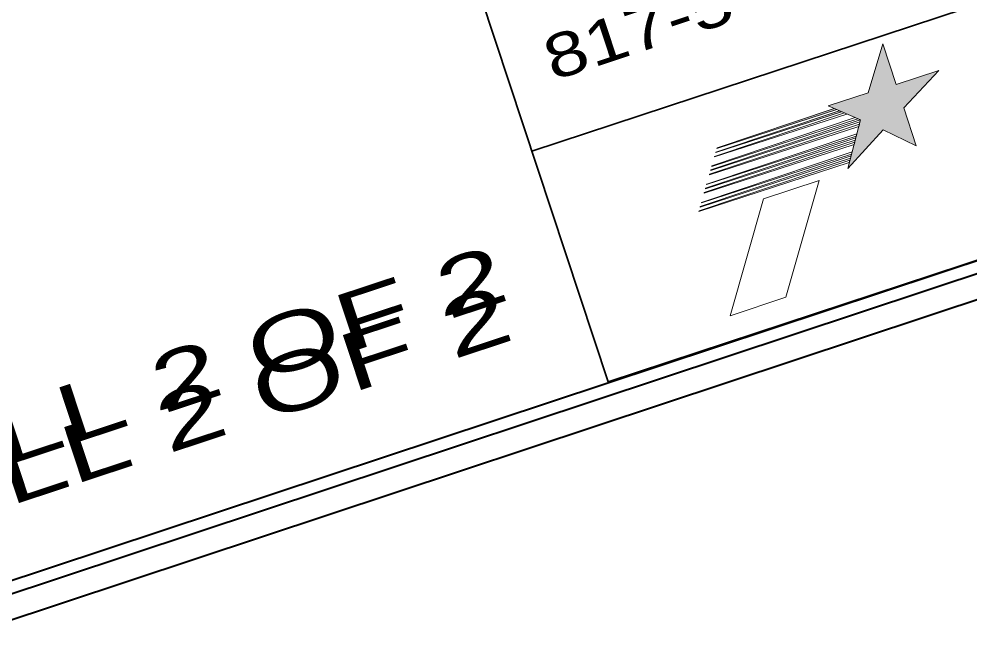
# Model space of a CAD drawing. Extents: x 2355803 to 2371254, y 6970215 to 6985302.
# Drawn here: x 2370231.3 to 2370614.5, y 6977989.2 to 6978236.6 of the extents above; entities that cross this region are included whole.
import ezdxf

# ---------------------------------------------------------------- set-up
doc = ezdxf.new("R2010")
doc.units = 0
doc.header["$LTSCALE"] = 7.1
doc.layers.add('19', color=7, linetype='Continuous', lineweight=13)
doc.layers.add('8', color=7, linetype='Continuous', lineweight=13)

msp = doc.modelspace()

# ---------------------------------------------------------------- hatches: boundary and pattern name
at = {"layer": '19'}
for points in [[(2370579.296, 6978226.596), (2370573.396, 6978206.854), (2370557.342, 6978201.552), (2370570.392, 6978195.93), (2370565.25, 6978176.42), (2370579.562, 6978191.926), (2370592.858, 6978185.542), (2370587.8, 6978200.856), (2370601.892, 6978215.84), (2370584.726, 6978210.162)], [(2370512.108, 6978182.992), (2370561.742, 6978199.652), (2370562.72, 6978199.22), (2370512.036, 6978182.78)], [(2370512.582, 6978184.658), (2370559.788, 6978200.482), (2370560.762, 6978200.09), (2370512.546, 6978184.424)]]:
    msp.add_hatch(color=256, dxfattribs=at).paths.add_polyline_path(points)
at = {"layer": '8'}
for points in [[(2370579.296, 6978226.596), (2370573.396, 6978206.854), (2370557.342, 6978201.552), (2370570.392, 6978195.93), (2370565.25, 6978176.42), (2370579.562, 6978191.926), (2370592.858, 6978185.542), (2370587.8, 6978200.856), (2370601.892, 6978215.84), (2370584.726, 6978210.162)], [(2370512.108, 6978182.992), (2370561.742, 6978199.652), (2370562.72, 6978199.22), (2370512.036, 6978182.78)], [(2370512.582, 6978184.658), (2370559.788, 6978200.482), (2370560.762, 6978200.09), (2370512.546, 6978184.424)]]:
    msp.add_hatch(color=256, dxfattribs=at).paths.add_polyline_path(points)

# ---------------------------------------------------------------- linework, layer by layer
at = {"layer": '19', "lineweight": 35}
for p, q in [((2370247.37, 6978760.29), (2370468.692, 6978090.342)), ((2371235.212, 6978343.566), (2370468.692, 6978090.342)), ((2370886.828, 6978331.606), (2370437.974, 6978183.324))]:
    msp.add_line(p, q, dxfattribs=at)
at = {"layer": '19', "lineweight": 40}
msp.add_lwpolyline([(2371235.04, 6978344.083), (2356889.216, 6973586.555), (2355819.061, 6976813.747)], dxfattribs=at)
at = {"layer": '19'}
for points in [[(2370579.296, 6978226.596), (2370573.396, 6978206.854), (2370557.342, 6978201.552), (2370570.392, 6978195.93), (2370565.25, 6978176.42), (2370579.562, 6978191.926), (2370592.858, 6978185.542), (2370587.8, 6978200.856), (2370601.892, 6978215.84), (2370584.726, 6978210.162)], [(2370511.594, 6978181.204), (2370563.88, 6978198.728), (2370564.84, 6978198.31), (2370511.57, 6978180.99)], [(2370512.108, 6978182.992), (2370561.742, 6978199.652), (2370562.72, 6978199.22), (2370512.036, 6978182.78)], [(2370512.582, 6978184.658), (2370559.788, 6978200.482), (2370560.762, 6978200.09), (2370512.546, 6978184.424)], [(2370509.55, 6978174.006), (2370569.96, 6978194.278), (2370569.704, 6978193.324), (2370509.528, 6978173.786)], [(2370510.038, 6978175.79), (2370570.166, 6978196), (2370570.38, 6978195.926), (2370570.158, 6978195.106), (2370510.002, 6978175.55)], [(2370510.528, 6978177.442), (2370568.26, 6978196.844), (2370569.354, 6978196.356), (2370510.48, 6978177.21)], [(2370508.414, 6978170.064), (2370568.926, 6978190.35), (2370568.682, 6978189.434), (2370508.36, 6978169.85)], [(2370507.43, 6978166.646), (2370568.014, 6978186.948), (2370567.77, 6978186.038), (2370507.39, 6978166.406)], [(2370507.918, 6978168.416), (2370568.48, 6978188.71), (2370568.248, 6978187.814), (2370507.894, 6978168.2)], [(2370506.298, 6978162.698), (2370566.99, 6978183.05), (2370566.756, 6978182.186), (2370506.248, 6978162.474)], [(2370505.322, 6978159.274), (2370566.09, 6978179.654), (2370565.846, 6978178.782), (2370505.258, 6978159.068)], [(2370505.802, 6978161.068), (2370566.566, 6978181.414), (2370566.33, 6978180.558), (2370505.766, 6978160.83)], [(2370531.304, 6978164.104), (2370517.858, 6978117.048), (2370540.252, 6978124.448), (2370553.682, 6978171.504)]]:
    msp.add_lwpolyline(points, close=True, dxfattribs=at)
at = {"layer": '8', "lineweight": 35}
for p, q in [((2370247.37, 6978760.29), (2370468.692, 6978090.342)), ((2371235.212, 6978343.566), (2370468.692, 6978090.342)), ((2370886.828, 6978331.606), (2370437.974, 6978183.324))]:
    msp.add_line(p, q, dxfattribs=at)
at = {"layer": '8', "lineweight": 40}
for p, q in [((2371241.36, 6978340.911), (2356886.044, 6973580.235)), ((2371231.868, 6978337.763), (2356886.044, 6973580.235)), ((2371254, 6978334.567), (2356879.7, 6973567.595))]:
    msp.add_line(p, q, dxfattribs=at)
at = {"layer": '8'}
for points in [[(2370579.296, 6978226.596), (2370573.396, 6978206.854), (2370557.342, 6978201.552), (2370570.392, 6978195.93), (2370565.25, 6978176.42), (2370579.562, 6978191.926), (2370592.858, 6978185.542), (2370587.8, 6978200.856), (2370601.892, 6978215.84), (2370584.726, 6978210.162)], [(2370511.594, 6978181.204), (2370563.88, 6978198.728), (2370564.84, 6978198.31), (2370511.57, 6978180.99)], [(2370512.108, 6978182.992), (2370561.742, 6978199.652), (2370562.72, 6978199.22), (2370512.036, 6978182.78)], [(2370512.582, 6978184.658), (2370559.788, 6978200.482), (2370560.762, 6978200.09), (2370512.546, 6978184.424)], [(2370509.55, 6978174.006), (2370569.96, 6978194.278), (2370569.704, 6978193.324), (2370509.528, 6978173.786)], [(2370510.038, 6978175.79), (2370570.166, 6978196), (2370570.38, 6978195.926), (2370570.158, 6978195.106), (2370510.002, 6978175.55)], [(2370510.528, 6978177.442), (2370568.26, 6978196.844), (2370569.354, 6978196.356), (2370510.48, 6978177.21)], [(2370508.414, 6978170.064), (2370568.926, 6978190.35), (2370568.682, 6978189.434), (2370508.36, 6978169.85)], [(2370507.43, 6978166.646), (2370568.014, 6978186.948), (2370567.77, 6978186.038), (2370507.39, 6978166.406)], [(2370507.918, 6978168.416), (2370568.48, 6978188.71), (2370568.248, 6978187.814), (2370507.894, 6978168.2)], [(2370506.298, 6978162.698), (2370566.99, 6978183.05), (2370566.756, 6978182.186), (2370506.248, 6978162.474)], [(2370505.322, 6978159.274), (2370566.09, 6978179.654), (2370565.846, 6978178.782), (2370505.258, 6978159.068)], [(2370505.802, 6978161.068), (2370566.566, 6978181.414), (2370566.33, 6978180.558), (2370505.766, 6978160.83)], [(2370531.304, 6978164.104), (2370517.858, 6978117.048), (2370540.252, 6978124.448), (2370553.682, 6978171.504)]]:
    msp.add_lwpolyline(points, close=True, dxfattribs=at)

# ---------------------------------------------------------------- texts
at = {"layer": '19'}
for s, height, width, p in [('817-545-0891', 17.63, 1.3, (2370446.43, 6978211.596)), ('ROLL 2 OF 2', 23.33, 1.55, (2370156.733, 6978033.598))]:
    msp.add_text(s, height=height, rotation=18.281, dxfattribs=dict(at, width=width)).set_placement(p)
at = {"layer": '8'}
for s, height, width, p in [('817-545-0891', 17.63, 1.3, (2370446.43, 6978211.596)), ('ROLL 2 OF 2', 23.33, 1.55, (2370158.673, 6978017.559))]:
    msp.add_text(s, height=height, rotation=18.281, dxfattribs=dict(at, width=width)).set_placement(p)

doc.saveas('drawing.dxf')
